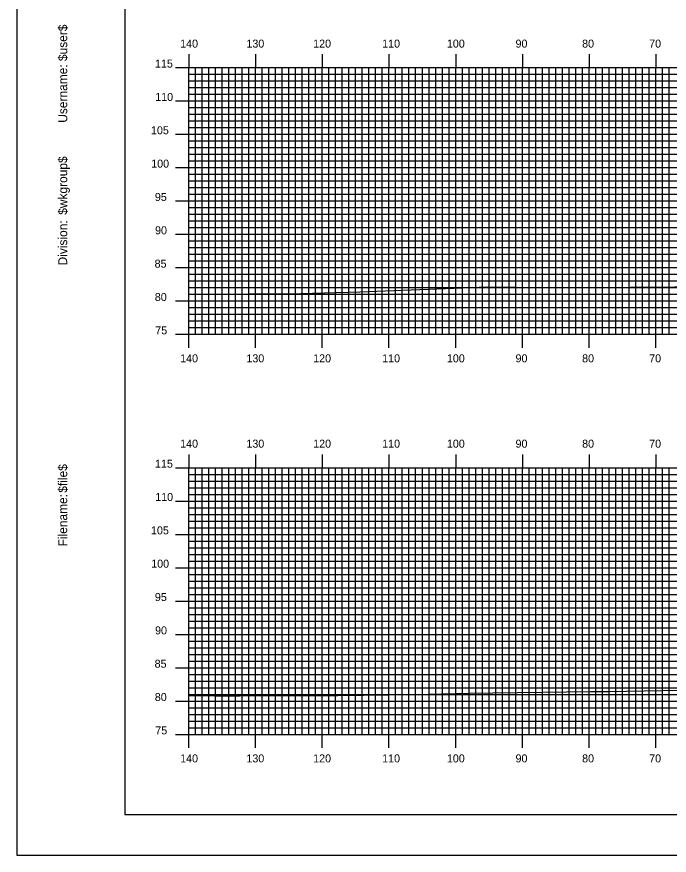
# Model space of a CAD drawing. Extents: x 1759823 to 1760167, y 442591 to 442811.
# Drawn here: x 1759823.4 to 1759921.2, y 442590.5 to 442716.3 of the extents above; entities that cross this region are included whole.
import ezdxf

# ---------------------------------------------------------------- set-up
doc = ezdxf.new("R2010")
doc.units = 0
for name, color, linetype in [('BORDER', 7, 'Continuous'), ('H_V ANNOTATION', 7, 'Continuous'), ('MAJOR', 7, 'Continuous'), ('MINOR', 7, 'Continuous'), ('PLOT BOUNDARY', 7, 'Continuous'), ('S_Roadway_Centerline', 7, 'Continuous')]:
    doc.layers.add(name, color=color, linetype=linetype)

msp = doc.modelspace()

# ---------------------------------------------------------------- linework, layer by layer
at = {"layer": 'BORDER'}
msp.add_lwpolyline([(1759839.59, 442596.67), (1760159.59, 442596.67), (1760159.59, 442806.67), (1759839.59, 442806.67)], close=True, dxfattribs=at)
at = {"layer": 'MAJOR'}
for p, q in [((1759849.19, 442710.67), (1759849.19, 442708.67)), ((1759859.19, 442710.67), (1759859.19, 442708.67)), ((1759869.19, 442710.67), (1759869.19, 442708.67)), ((1759879.19, 442710.67), (1759879.19, 442708.67)), ((1759889.19, 442710.67), (1759889.19, 442708.67)), ((1759899.19, 442710.67), (1759899.19, 442708.67)), ((1759909.19, 442710.67), (1759909.19, 442708.67)), ((1759919.19, 442710.67), (1759919.19, 442708.67)), ((1759847.18, 442708.67), (1759849.19, 442708.67)), ((1759849.19, 442708.67), (1760129.19, 442708.67)), ((1759849.19, 442668.67), (1759849.19, 442708.67)), ((1759849.19, 442668.67), (1759849.19, 442708.67)), ((1759849.19, 442708.67), (1760129.19, 442708.67)), ((1759859.19, 442668.67), (1759859.19, 442708.67)), ((1759869.19, 442668.67), (1759869.19, 442708.67)), ((1759879.19, 442668.67), (1759879.19, 442708.67)), ((1759889.19, 442668.67), (1759889.19, 442708.67)), ((1759899.19, 442668.67), (1759899.19, 442708.67)), ((1759909.19, 442668.67), (1759909.19, 442708.67)), ((1759919.19, 442668.67), (1759919.19, 442708.67)), ((1759847.18, 442703.67), (1759849.19, 442703.67)), ((1759849.19, 442703.67), (1760129.19, 442703.67)), ((1759847.18, 442698.67), (1759849.19, 442698.67)), ((1759849.19, 442698.67), (1760129.19, 442698.67)), ((1759847.18, 442693.67), (1759849.19, 442693.67)), ((1759849.19, 442693.67), (1760129.19, 442693.67)), ((1759847.18, 442688.67), (1759849.19, 442688.67)), ((1759849.19, 442688.67), (1760129.19, 442688.67)), ((1759847.18, 442683.67), (1759849.19, 442683.67)), ((1759849.19, 442683.67), (1760129.19, 442683.67)), ((1759847.18, 442678.67), (1759849.19, 442678.67)), ((1759849.19, 442678.67), (1760129.19, 442678.67)), ((1759847.18, 442673.67), (1759849.19, 442673.67)), ((1759849.19, 442673.67), (1760129.19, 442673.67)), ((1759847.18, 442668.67), (1759849.19, 442668.67)), ((1759849.19, 442668.67), (1760129.19, 442668.67)), ((1759849.19, 442668.67), (1760129.19, 442668.67)), ((1759849.19, 442666.66), (1759849.19, 442668.67)), ((1759859.19, 442666.66), (1759859.19, 442668.67)), ((1759869.19, 442666.66), (1759869.19, 442668.67)), ((1759879.19, 442666.66), (1759879.19, 442668.67)), ((1759889.19, 442666.66), (1759889.19, 442668.67)), ((1759899.19, 442666.66), (1759899.19, 442668.67)), ((1759909.19, 442666.66), (1759909.19, 442668.67)), ((1759919.19, 442666.66), (1759919.19, 442668.67)), ((1759849.19, 442650.67), (1759849.19, 442648.67)), ((1759859.19, 442650.67), (1759859.19, 442648.67)), ((1759869.19, 442650.67), (1759869.19, 442648.67)), ((1759879.19, 442650.67), (1759879.19, 442648.67)), ((1759889.19, 442650.67), (1759889.19, 442648.67)), ((1759899.19, 442650.67), (1759899.19, 442648.67)), ((1759909.19, 442650.67), (1759909.19, 442648.67)), ((1759919.19, 442650.67), (1759919.19, 442648.67)), ((1759847.18, 442648.67), (1759849.19, 442648.67)), ((1759849.19, 442648.67), (1760129.19, 442648.67)), ((1759849.19, 442608.67), (1759849.19, 442648.67)), ((1759849.19, 442608.67), (1759849.19, 442648.67)), ((1759849.19, 442648.67), (1760129.19, 442648.67)), ((1759859.19, 442608.67), (1759859.19, 442648.67)), ((1759869.19, 442608.67), (1759869.19, 442648.67)), ((1759879.19, 442608.67), (1759879.19, 442648.67)), ((1759889.19, 442608.67), (1759889.19, 442648.67)), ((1759899.19, 442608.67), (1759899.19, 442648.67)), ((1759909.19, 442608.67), (1759909.19, 442648.67)), ((1759919.19, 442608.67), (1759919.19, 442648.67)), ((1759847.18, 442643.67), (1759849.19, 442643.67)), ((1759849.19, 442643.67), (1760129.19, 442643.67)), ((1759847.18, 442638.67), (1759849.19, 442638.67)), ((1759849.19, 442638.67), (1760129.19, 442638.67)), ((1759847.18, 442633.67), (1759849.19, 442633.67)), ((1759849.19, 442633.67), (1760129.19, 442633.67)), ((1759847.18, 442628.67), (1759849.19, 442628.67)), ((1759849.19, 442628.67), (1760129.19, 442628.67)), ((1759847.18, 442623.67), (1759849.19, 442623.67)), ((1759849.19, 442623.67), (1760129.19, 442623.67)), ((1759847.18, 442618.67), (1759849.19, 442618.67)), ((1759849.19, 442618.67), (1760129.19, 442618.67)), ((1759847.18, 442613.67), (1759849.19, 442613.67)), ((1759849.19, 442613.67), (1760129.19, 442613.67)), ((1759847.18, 442608.67), (1759849.19, 442608.67)), ((1759849.19, 442608.67), (1760129.19, 442608.67)), ((1759849.19, 442608.67), (1760129.19, 442608.67)), ((1759849.19, 442606.66), (1759849.19, 442608.67)), ((1759859.19, 442606.66), (1759859.19, 442608.67)), ((1759869.19, 442606.66), (1759869.19, 442608.67)), ((1759879.19, 442606.66), (1759879.19, 442608.67)), ((1759889.19, 442606.66), (1759889.19, 442608.67)), ((1759899.19, 442606.66), (1759899.19, 442608.67)), ((1759909.19, 442606.66), (1759909.19, 442608.67)), ((1759919.19, 442606.66), (1759919.19, 442608.67))]:
    msp.add_line(p, q, dxfattribs=at)
at = {"layer": 'MINOR'}
for p, q in [((1759850.19, 442668.67), (1759850.19, 442708.67)), ((1759851.19, 442668.67), (1759851.19, 442708.67)), ((1759852.19, 442668.67), (1759852.19, 442708.67)), ((1759853.19, 442668.67), (1759853.19, 442708.67)), ((1759854.19, 442668.67), (1759854.19, 442708.67)), ((1759855.19, 442668.67), (1759855.19, 442708.67)), ((1759856.19, 442668.67), (1759856.19, 442708.67)), ((1759857.19, 442668.67), (1759857.19, 442708.67)), ((1759858.19, 442668.67), (1759858.19, 442708.67)), ((1759860.19, 442668.67), (1759860.19, 442708.67)), ((1759861.19, 442668.67), (1759861.19, 442708.67)), ((1759862.19, 442668.67), (1759862.19, 442708.67)), ((1759863.19, 442668.67), (1759863.19, 442708.67)), ((1759864.19, 442668.67), (1759864.19, 442708.67)), ((1759865.19, 442668.67), (1759865.19, 442708.67)), ((1759866.19, 442668.67), (1759866.19, 442708.67)), ((1759867.19, 442668.67), (1759867.19, 442708.67)), ((1759868.19, 442668.67), (1759868.19, 442708.67)), ((1759870.19, 442668.67), (1759870.19, 442708.67)), ((1759871.19, 442668.67), (1759871.19, 442708.67)), ((1759872.19, 442668.67), (1759872.19, 442708.67)), ((1759873.19, 442668.67), (1759873.19, 442708.67)), ((1759874.19, 442668.67), (1759874.19, 442708.67)), ((1759875.19, 442668.67), (1759875.19, 442708.67)), ((1759876.19, 442668.67), (1759876.19, 442708.67)), ((1759877.19, 442668.67), (1759877.19, 442708.67)), ((1759878.19, 442668.67), (1759878.19, 442708.67)), ((1759880.19, 442668.67), (1759880.19, 442708.67)), ((1759881.19, 442668.67), (1759881.19, 442708.67)), ((1759882.19, 442668.67), (1759882.19, 442708.67)), ((1759883.19, 442668.67), (1759883.19, 442708.67)), ((1759884.19, 442668.67), (1759884.19, 442708.67)), ((1759885.19, 442668.67), (1759885.19, 442708.67)), ((1759886.19, 442668.67), (1759886.19, 442708.67)), ((1759887.19, 442668.67), (1759887.19, 442708.67)), ((1759888.19, 442668.67), (1759888.19, 442708.67)), ((1759890.19, 442668.67), (1759890.19, 442708.67)), ((1759891.19, 442668.67), (1759891.19, 442708.67)), ((1759892.19, 442668.67), (1759892.19, 442708.67)), ((1759893.19, 442668.67), (1759893.19, 442708.67)), ((1759894.19, 442668.67), (1759894.19, 442708.67)), ((1759895.19, 442668.67), (1759895.19, 442708.67)), ((1759896.19, 442668.67), (1759896.19, 442708.67)), ((1759897.19, 442668.67), (1759897.19, 442708.67)), ((1759898.19, 442668.67), (1759898.19, 442708.67)), ((1759900.19, 442668.67), (1759900.19, 442708.67)), ((1759901.19, 442668.67), (1759901.19, 442708.67)), ((1759902.19, 442668.67), (1759902.19, 442708.67)), ((1759903.19, 442668.67), (1759903.19, 442708.67)), ((1759904.19, 442668.67), (1759904.19, 442708.67)), ((1759905.19, 442668.67), (1759905.19, 442708.67)), ((1759906.19, 442668.67), (1759906.19, 442708.67)), ((1759907.19, 442668.67), (1759907.19, 442708.67)), ((1759908.19, 442668.67), (1759908.19, 442708.67)), ((1759910.19, 442668.67), (1759910.19, 442708.67)), ((1759911.19, 442668.67), (1759911.19, 442708.67)), ((1759912.19, 442668.67), (1759912.19, 442708.67)), ((1759913.19, 442668.67), (1759913.19, 442708.67)), ((1759914.19, 442668.67), (1759914.19, 442708.67)), ((1759915.19, 442668.67), (1759915.19, 442708.67)), ((1759916.19, 442668.67), (1759916.19, 442708.67)), ((1759917.19, 442668.67), (1759917.19, 442708.67)), ((1759918.19, 442668.67), (1759918.19, 442708.67)), ((1759920.19, 442668.67), (1759920.19, 442708.67)), ((1759921.19, 442668.67), (1759921.19, 442708.67)), ((1759849.19, 442707.67), (1760129.19, 442707.67)), ((1759849.19, 442707.67), (1759851.19, 442707.67)), ((1759849.19, 442706.67), (1760129.19, 442706.67)), ((1759849.19, 442706.67), (1759851.19, 442706.67)), ((1759849.19, 442705.67), (1760129.19, 442705.67)), ((1759849.19, 442705.67), (1759851.19, 442705.67)), ((1759849.19, 442704.67), (1760129.19, 442704.67)), ((1759849.19, 442704.67), (1759851.19, 442704.67)), ((1759849.19, 442702.67), (1760129.19, 442702.67)), ((1759849.19, 442702.67), (1759851.19, 442702.67)), ((1759849.19, 442701.67), (1760129.19, 442701.67)), ((1759849.19, 442701.67), (1759851.19, 442701.67)), ((1759849.19, 442700.67), (1760129.19, 442700.67)), ((1759849.19, 442700.67), (1759851.19, 442700.67)), ((1759849.19, 442699.67), (1760129.19, 442699.67)), ((1759849.19, 442699.67), (1759851.19, 442699.67)), ((1759849.19, 442697.67), (1760129.19, 442697.67)), ((1759849.19, 442697.67), (1759851.19, 442697.67)), ((1759849.19, 442696.67), (1760129.19, 442696.67)), ((1759849.19, 442696.67), (1759851.19, 442696.67)), ((1759849.19, 442695.67), (1760129.19, 442695.67)), ((1759849.19, 442695.67), (1759851.19, 442695.67)), ((1759849.19, 442694.67), (1760129.19, 442694.67)), ((1759849.19, 442694.67), (1759851.19, 442694.67)), ((1759849.19, 442692.67), (1760129.19, 442692.67)), ((1759849.19, 442692.67), (1759851.19, 442692.67)), ((1759849.19, 442691.67), (1760129.19, 442691.67)), ((1759849.19, 442691.67), (1759851.19, 442691.67)), ((1759849.19, 442690.67), (1760129.19, 442690.67)), ((1759849.19, 442690.67), (1759851.19, 442690.67)), ((1759849.19, 442689.67), (1760129.19, 442689.67)), ((1759849.19, 442689.67), (1759851.19, 442689.67)), ((1759849.19, 442687.67), (1760129.19, 442687.67)), ((1759849.19, 442687.67), (1759851.19, 442687.67)), ((1759849.19, 442686.67), (1760129.19, 442686.67)), ((1759849.19, 442686.67), (1759851.19, 442686.67)), ((1759849.19, 442685.67), (1760129.19, 442685.67)), ((1759849.19, 442685.67), (1759851.19, 442685.67)), ((1759849.19, 442684.67), (1760129.19, 442684.67)), ((1759849.19, 442684.67), (1759851.19, 442684.67)), ((1759849.19, 442682.67), (1760129.19, 442682.67)), ((1759849.19, 442682.67), (1759851.19, 442682.67)), ((1759849.19, 442681.67), (1760129.19, 442681.67)), ((1759849.19, 442681.67), (1759851.19, 442681.67)), ((1759849.19, 442680.67), (1760129.19, 442680.67)), ((1759849.19, 442680.67), (1759851.19, 442680.67)), ((1759849.19, 442679.67), (1760129.19, 442679.67)), ((1759849.19, 442679.67), (1759851.19, 442679.67)), ((1759849.19, 442677.67), (1760129.19, 442677.67)), ((1759849.19, 442677.67), (1759851.19, 442677.67)), ((1759849.19, 442676.67), (1760129.19, 442676.67)), ((1759849.19, 442676.67), (1759851.19, 442676.67)), ((1759849.19, 442675.67), (1760129.19, 442675.67)), ((1759849.19, 442675.67), (1759851.19, 442675.67)), ((1759849.19, 442674.67), (1760129.19, 442674.67)), ((1759849.19, 442674.67), (1759851.19, 442674.67)), ((1759849.19, 442672.67), (1760129.19, 442672.67)), ((1759849.19, 442672.67), (1759851.19, 442672.67)), ((1759849.19, 442671.67), (1760129.19, 442671.67)), ((1759849.19, 442671.67), (1759851.19, 442671.67)), ((1759849.19, 442670.67), (1760129.19, 442670.67)), ((1759849.19, 442670.67), (1759851.19, 442670.67)), ((1759849.19, 442669.67), (1760129.19, 442669.67)), ((1759849.19, 442669.67), (1759851.19, 442669.67)), ((1759850.19, 442608.67), (1759850.19, 442648.67)), ((1759851.19, 442608.67), (1759851.19, 442648.67)), ((1759852.19, 442608.67), (1759852.19, 442648.67)), ((1759853.19, 442608.67), (1759853.19, 442648.67)), ((1759854.19, 442608.67), (1759854.19, 442648.67)), ((1759855.19, 442608.67), (1759855.19, 442648.67)), ((1759856.19, 442608.67), (1759856.19, 442648.67)), ((1759857.19, 442608.67), (1759857.19, 442648.67)), ((1759858.19, 442608.67), (1759858.19, 442648.67)), ((1759860.19, 442608.67), (1759860.19, 442648.67)), ((1759861.19, 442608.67), (1759861.19, 442648.67)), ((1759862.19, 442608.67), (1759862.19, 442648.67)), ((1759863.19, 442608.67), (1759863.19, 442648.67)), ((1759864.19, 442608.67), (1759864.19, 442648.67)), ((1759865.19, 442608.67), (1759865.19, 442648.67)), ((1759866.19, 442608.67), (1759866.19, 442648.67)), ((1759867.19, 442608.67), (1759867.19, 442648.67)), ((1759868.19, 442608.67), (1759868.19, 442648.67)), ((1759870.19, 442608.67), (1759870.19, 442648.67)), ((1759871.19, 442608.67), (1759871.19, 442648.67)), ((1759872.19, 442608.67), (1759872.19, 442648.67)), ((1759873.19, 442608.67), (1759873.19, 442648.67)), ((1759874.19, 442608.67), (1759874.19, 442648.67)), ((1759875.19, 442608.67), (1759875.19, 442648.67)), ((1759876.19, 442608.67), (1759876.19, 442648.67)), ((1759877.19, 442608.67), (1759877.19, 442648.67)), ((1759878.19, 442608.67), (1759878.19, 442648.67)), ((1759880.19, 442608.67), (1759880.19, 442648.67)), ((1759881.19, 442608.67), (1759881.19, 442648.67)), ((1759882.19, 442608.67), (1759882.19, 442648.67)), ((1759883.19, 442608.67), (1759883.19, 442648.67)), ((1759884.19, 442608.67), (1759884.19, 442648.67)), ((1759885.19, 442608.67), (1759885.19, 442648.67)), ((1759886.19, 442608.67), (1759886.19, 442648.67)), ((1759887.19, 442608.67), (1759887.19, 442648.67)), ((1759888.19, 442608.67), (1759888.19, 442648.67)), ((1759890.19, 442608.67), (1759890.19, 442648.67)), ((1759891.19, 442608.67), (1759891.19, 442648.67)), ((1759892.19, 442608.67), (1759892.19, 442648.67)), ((1759893.19, 442608.67), (1759893.19, 442648.67)), ((1759894.19, 442608.67), (1759894.19, 442648.67)), ((1759895.19, 442608.67), (1759895.19, 442648.67)), ((1759896.19, 442608.67), (1759896.19, 442648.67)), ((1759897.19, 442608.67), (1759897.19, 442648.67)), ((1759898.19, 442608.67), (1759898.19, 442648.67)), ((1759900.19, 442608.67), (1759900.19, 442648.67)), ((1759901.19, 442608.67), (1759901.19, 442648.67)), ((1759902.19, 442608.67), (1759902.19, 442648.67)), ((1759903.19, 442608.67), (1759903.19, 442648.67)), ((1759904.19, 442608.67), (1759904.19, 442648.67)), ((1759905.19, 442608.67), (1759905.19, 442648.67)), ((1759906.19, 442608.67), (1759906.19, 442648.67)), ((1759907.19, 442608.67), (1759907.19, 442648.67)), ((1759908.19, 442608.67), (1759908.19, 442648.67)), ((1759910.19, 442608.67), (1759910.19, 442648.67)), ((1759911.19, 442608.67), (1759911.19, 442648.67)), ((1759912.19, 442608.67), (1759912.19, 442648.67)), ((1759913.19, 442608.67), (1759913.19, 442648.67)), ((1759914.19, 442608.67), (1759914.19, 442648.67)), ((1759915.19, 442608.67), (1759915.19, 442648.67)), ((1759916.19, 442608.67), (1759916.19, 442648.67)), ((1759917.19, 442608.67), (1759917.19, 442648.67)), ((1759918.19, 442608.67), (1759918.19, 442648.67)), ((1759920.19, 442608.67), (1759920.19, 442648.67)), ((1759921.19, 442608.67), (1759921.19, 442648.67)), ((1759849.19, 442647.67), (1760129.19, 442647.67)), ((1759849.19, 442647.67), (1759851.19, 442647.67)), ((1759849.19, 442646.67), (1760129.19, 442646.67)), ((1759849.19, 442646.67), (1759851.19, 442646.67)), ((1759849.19, 442645.67), (1760129.19, 442645.67)), ((1759849.19, 442645.67), (1759851.19, 442645.67)), ((1759849.19, 442644.67), (1760129.19, 442644.67)), ((1759849.19, 442644.67), (1759851.19, 442644.67)), ((1759849.19, 442642.67), (1760129.19, 442642.67)), ((1759849.19, 442642.67), (1759851.19, 442642.67)), ((1759849.19, 442641.67), (1760129.19, 442641.67)), ((1759849.19, 442641.67), (1759851.19, 442641.67)), ((1759849.19, 442640.67), (1760129.19, 442640.67)), ((1759849.19, 442640.67), (1759851.19, 442640.67)), ((1759849.19, 442639.67), (1760129.19, 442639.67)), ((1759849.19, 442639.67), (1759851.19, 442639.67)), ((1759849.19, 442637.67), (1760129.19, 442637.67)), ((1759849.19, 442637.67), (1759851.19, 442637.67)), ((1759849.19, 442636.67), (1760129.19, 442636.67)), ((1759849.19, 442636.67), (1759851.19, 442636.67)), ((1759849.19, 442635.67), (1760129.19, 442635.67)), ((1759849.19, 442635.67), (1759851.19, 442635.67)), ((1759849.19, 442634.67), (1760129.19, 442634.67)), ((1759849.19, 442634.67), (1759851.19, 442634.67)), ((1759849.19, 442632.67), (1760129.19, 442632.67)), ((1759849.19, 442632.67), (1759851.19, 442632.67)), ((1759849.19, 442631.67), (1760129.19, 442631.67)), ((1759849.19, 442631.67), (1759851.19, 442631.67)), ((1759849.19, 442630.67), (1760129.19, 442630.67)), ((1759849.19, 442630.67), (1759851.19, 442630.67)), ((1759849.19, 442629.67), (1760129.19, 442629.67)), ((1759849.19, 442629.67), (1759851.19, 442629.67)), ((1759849.19, 442627.67), (1760129.19, 442627.67)), ((1759849.19, 442627.67), (1759851.19, 442627.67)), ((1759849.19, 442626.67), (1760129.19, 442626.67)), ((1759849.19, 442626.67), (1759851.19, 442626.67)), ((1759849.19, 442625.67), (1760129.19, 442625.67)), ((1759849.19, 442625.67), (1759851.19, 442625.67)), ((1759849.19, 442624.67), (1760129.19, 442624.67)), ((1759849.19, 442624.67), (1759851.19, 442624.67)), ((1759849.19, 442622.67), (1760129.19, 442622.67)), ((1759849.19, 442622.67), (1759851.19, 442622.67)), ((1759849.19, 442621.67), (1760129.19, 442621.67)), ((1759849.19, 442621.67), (1759851.19, 442621.67)), ((1759849.19, 442620.67), (1760129.19, 442620.67)), ((1759849.19, 442620.67), (1759851.19, 442620.67)), ((1759849.19, 442619.67), (1760129.19, 442619.67)), ((1759849.19, 442619.67), (1759851.19, 442619.67)), ((1759849.19, 442617.67), (1760129.19, 442617.67)), ((1759849.19, 442617.67), (1759851.19, 442617.67)), ((1759849.19, 442616.67), (1760129.19, 442616.67)), ((1759849.19, 442616.67), (1759851.19, 442616.67)), ((1759849.19, 442615.67), (1760129.19, 442615.67)), ((1759849.19, 442615.67), (1759851.19, 442615.67)), ((1759849.19, 442614.67), (1760129.19, 442614.67)), ((1759849.19, 442614.67), (1759851.19, 442614.67)), ((1759849.19, 442612.67), (1760129.19, 442612.67)), ((1759849.19, 442612.67), (1759851.19, 442612.67)), ((1759849.19, 442611.67), (1760129.19, 442611.67)), ((1759849.19, 442611.67), (1759851.19, 442611.67)), ((1759849.19, 442610.67), (1760129.19, 442610.67)), ((1759849.19, 442610.67), (1759851.19, 442610.67)), ((1759849.19, 442609.67), (1760129.19, 442609.67)), ((1759849.19, 442609.67), (1759851.19, 442609.67))]:
    msp.add_line(p, q, dxfattribs=at)
at = {"layer": 'PLOT BOUNDARY'}
msp.add_lwpolyline([(1759823.4, 442590.55), (1760163.4, 442590.55), (1760163.4, 442810.55), (1759823.4, 442810.55)], close=True, dxfattribs=at)
at = {"layer": 'S_Roadway_Centerline'}
for points in [[(1759849.19, 442674.63), (1759858.16, 442674.72), (1759865.99, 442674.77), (1759874.83, 442675.02), (1759887.65, 442675.56), (1759893.92, 442675.79), (1759902.2, 442675.7), (1759906.13, 442675.62), (1759908.75, 442675.67), (1759928.63, 442675.84)], [(1759849.19, 442614.48), (1759850.03, 442614.49), (1759853.02, 442614.46), (1759856.78, 442614.45), (1759871.53, 442614.51), (1759883, 442614.67), (1759891.12, 442614.86), (1759909.44, 442615.1), (1759910.99, 442615.11), (1759912.12, 442615.12), (1759922.73, 442615.3)]]:
    msp.add_lwpolyline(points, dxfattribs=at)

# ---------------------------------------------------------------- texts
at = {"layer": 'BORDER'}
for s, p in [('$user$', (1759830.96, 442709.65)), ('$user$', (1759830.96, 442709.65)), ('Username:', (1759830.96, 442700.4)), ('Username:', (1759830.96, 442700.4)), ('$wkgroup$', (1759830.96, 442686.6)), ('$wkgroup$', (1759830.96, 442686.6)), ('Division:', (1759830.96, 442679)), ('Division:', (1759830.96, 442679)), ('$file$', (1759830.96, 442644.92)), ('$file$', (1759830.96, 442644.92)), ('Filename:', (1759830.96, 442636.86)), ('Filename:', (1759830.96, 442636.86))]:
    msp.add_text(s, height=1.339, rotation=90, dxfattribs=at).set_placement(p)
at = {"layer": 'H_V ANNOTATION'}
for s, p in [('140', (1759847.89, 442711.67)), ('130', (1759857.82, 442711.67)), ('120', (1759867.83, 442711.67)), ('110', (1759878.17, 442711.67)), ('100', (1759887.87, 442711.67)), ('90', (1759898.16, 442711.67)), ('80', (1759908.14, 442711.67)), ('70', (1759918.19, 442711.67)), ('115', (1759844.12, 442708.67)), ('110', (1759844.15, 442703.67)), ('105', (1759843.52, 442698.67)), ('100', (1759843.55, 442693.67)), ('95', (1759844.1, 442688.67)), ('90', (1759844.13, 442683.67)), ('85', (1759844.06, 442678.67)), ('80', (1759844.09, 442673.67)), ('75', (1759844.16, 442668.67)), ('140', (1759847.89, 442664.47)), ('130', (1759857.82, 442664.47)), ('120', (1759867.83, 442664.47)), ('110', (1759878.17, 442664.47)), ('100', (1759887.87, 442664.47)), ('90', (1759898.16, 442664.47)), ('80', (1759908.14, 442664.47)), ('70', (1759918.19, 442664.47)), ('140', (1759847.89, 442651.67)), ('130', (1759857.82, 442651.67)), ('120', (1759867.83, 442651.67)), ('110', (1759878.17, 442651.67)), ('100', (1759887.87, 442651.67)), ('90', (1759898.16, 442651.67)), ('80', (1759908.14, 442651.67)), ('70', (1759918.19, 442651.67)), ('115', (1759844.12, 442648.67)), ('110', (1759844.15, 442643.67)), ('105', (1759843.52, 442638.67)), ('100', (1759843.55, 442633.67)), ('95', (1759844.1, 442628.67)), ('90', (1759844.13, 442623.67)), ('85', (1759844.06, 442618.67)), ('80', (1759844.09, 442613.67)), ('75', (1759844.16, 442608.67)), ('140', (1759847.89, 442604.47)), ('130', (1759857.82, 442604.47)), ('120', (1759867.83, 442604.47)), ('110', (1759878.17, 442604.47)), ('100', (1759887.87, 442604.47)), ('90', (1759898.16, 442604.47)), ('80', (1759908.14, 442604.47)), ('70', (1759918.19, 442604.47))]:
    msp.add_text(s, height=1.2, dxfattribs=at).set_placement(p)
at = {"layer": 'MAJOR'}
for p in [(1759849.18, 442668.67), (1759849.18, 442608.67)]:
    msp.add_text('-', height=0.012, dxfattribs=at).set_placement(p)

doc.saveas('drawing.dxf')
